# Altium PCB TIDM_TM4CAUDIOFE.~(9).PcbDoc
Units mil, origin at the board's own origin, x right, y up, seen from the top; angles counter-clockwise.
Board outline 2200 x 1200 mil, 4 copper layers (Component Side, Ground Plane, Power Plane, Solder Side), stack 33.234 mil thick; 32 components, 22 nets, 109 pads, 0 vias.
Unrouted connection lines stored in the file: 53.
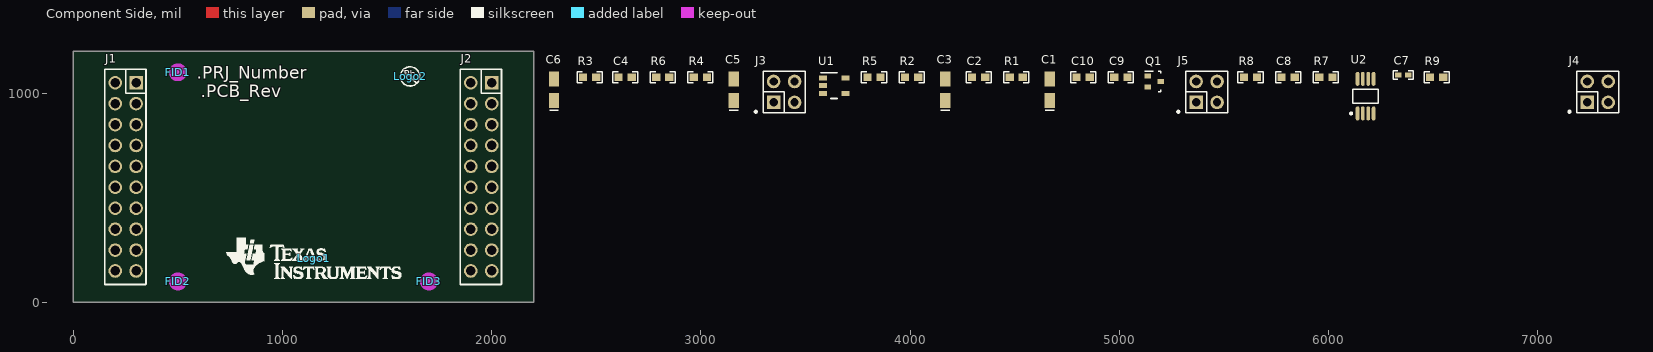
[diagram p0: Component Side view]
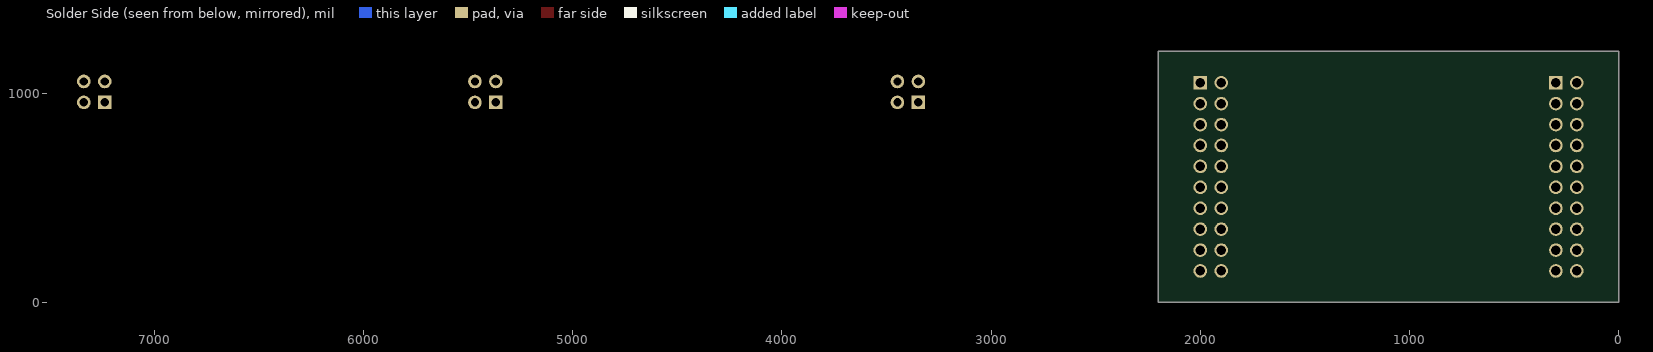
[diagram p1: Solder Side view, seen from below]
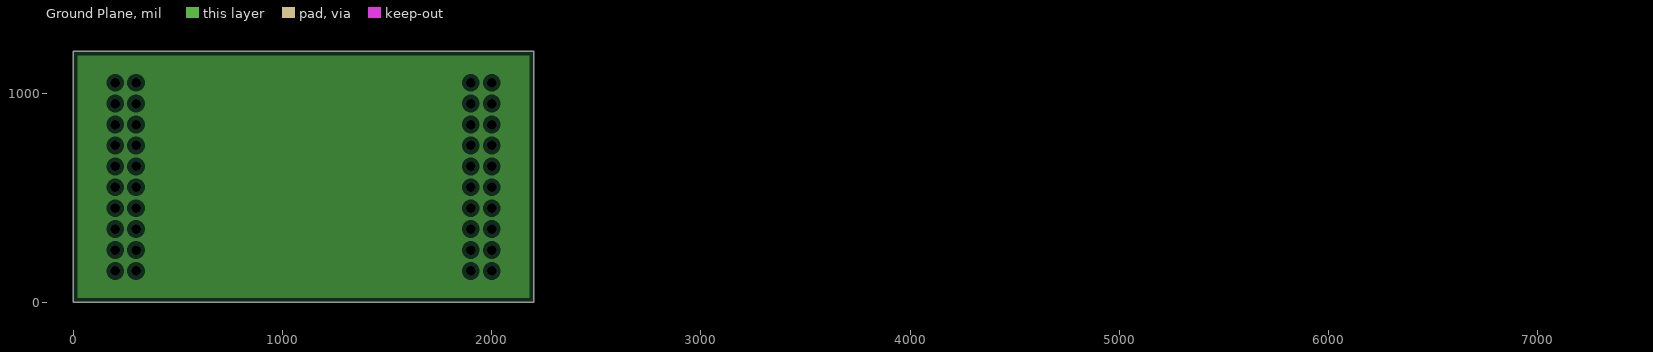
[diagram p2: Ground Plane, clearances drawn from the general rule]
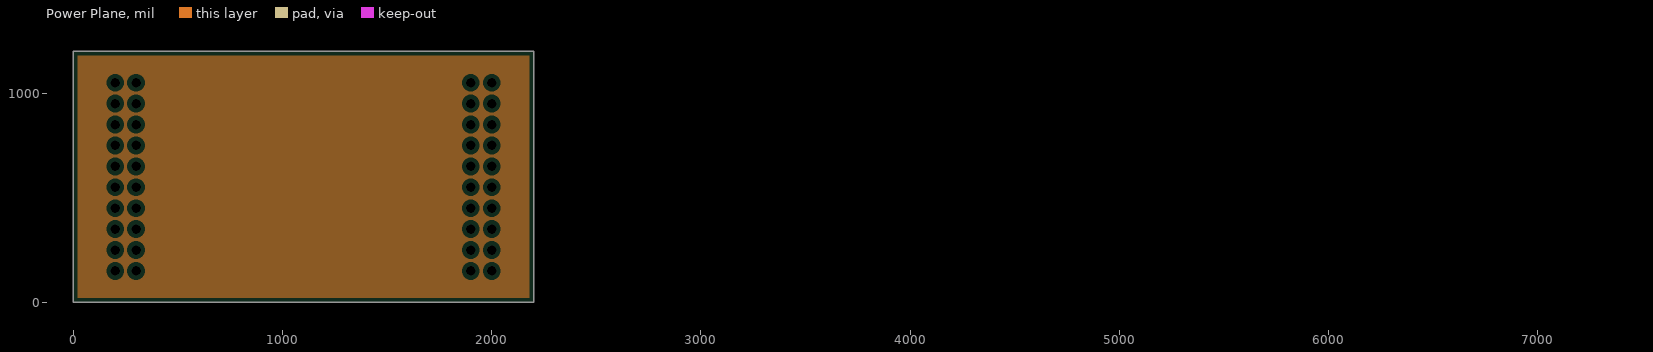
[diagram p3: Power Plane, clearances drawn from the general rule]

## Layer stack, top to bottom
Top Solder: solder mask 0.4, Solder Resist, Dk 3.5
Component Side: signal copper 1.4
Dielectric 1: core 12.6, FR-4, Dk 4.8
Ground Plane: plane copper 1.417
Dielectric 3: prepreg 5, Dk 4.2
Power Plane: plane copper 1.417
Dielectric 4: core 10, Dk 4.2
Solder Side: signal copper 1.4
Bottom Solder: solder mask 0.4, Solder Resist, Dk 3.5

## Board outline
0,0 0,1200 2200,1200 2200,0

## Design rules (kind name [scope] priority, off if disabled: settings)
AcuteAngle [All] p1: minimum=4.50000000000000E+0001 checktracksonly=FALSE
AssemblyTestPointUsage [All] p1: valid=2
Clearance Clearance_Keepouts [((IsTrack Or IsArc) And Not InPoly) And IsFree and IsKeepOut vs ((IsTrack Or IsArc) And Not InPoly) And IsFree and IsKeepOut] p1: gap=0
Clearance Clearance_BoardEdge_MountingHoles [OnCopper and InComponentClass('Mounting Holes') vs IsKeepOut] p2: gap=40
Clearance Clearance_BoardEdge_Poly [OnCopper and InPoly vs IsKeepOut] p3: gap=25
Clearance Clearance_BoardEdge [OnCopper and Not InComponentClass('Logo') and not InComponentClass('FiducialMark') and not InRegion(1000,500,4000,800) and Not IsKeepout vs IsKeepOut] p4: gap=75
Clearance Clearance_Poly [InPolygon] p5: gap=25
Clearance [All] p6: gap=7.87
ComponentClearance ComponentClearance_MountingHoles_FiducialMarks [InComponentClass('Mounting Holes') vs InComponentClass('FiducialMark')] p1: gap=50 collisioncheckmode=3 verticalgap=10 showdistances=FALSE
ComponentClearance ComponentClearance_Shunt [InComponentClass('Header') vs InComponentClass('Shunt')] p2: gap=0 collisioncheckmode=3 verticalgap=0 showdistances=FALSE
ComponentClearance ComponentClearance_Logo [InComponentClass('Logo')] p3: gap=50 collisioncheckmode=3 verticalgap=10 showdistances=FALSE
ComponentClearance ComponentClearance_ScrewToNut [(HasFootprint('NY PMS 440 0025 PH')) vs (HasFootprint('Keystone_1902C'))] p4: gap=5 collisioncheckmode=3 verticalgap=10 showdistances=FALSE
ComponentClearance ComponentClearance_MountingHoles [InComponentClass('Mounting Holes')] p5: gap=250 collisioncheckmode=3 verticalgap=100000 showdistances=FALSE
ComponentClearance ComponentClearance_SmallPassives [HasFootprint('0201*') or HasFootprint('0402*') or HasFootprint('0508') or HasFootprint('0603*') or HasFootprint('0612') or HasFootprint('0805*') or HasFootprint('0815*') or HasFootprint('0830*') or HasFootprint('1206*') or HasFootprint('1210*') or HasFootprint('1808*') or HasFootprint('1812*') or HasFootprint('1825*') or HasFootprint('2010*') or HasFootprint('2220*') or HasFootprint('2225*') or HasFootprint('2512*') or HasFootprint('2728*') or HasFootprint('3518*') vs HasFootprint('0201*') or HasFootprint('0402*') or HasFootprint('0508') or HasFootprint('0603*') or HasFootprint('0612') or HasFootprint('0805*') or HasFootprint('0815*') or HasFootprint('0830*') or HasFootprint('1206*') or HasFootprint('1210*') or HasFootprint('1808*') or HasFootprint('1812*') or HasFootprint('1825*') or HasFootprint('2010*') or HasFootprint('2220*') or HasFootprint('2225*') or HasFootprint('2512*') or HasFootprint('2728*') or HasFootprint('3518*')] p6: gap=20 collisioncheckmode=3 verticalgap=10 showdistances=FALSE
ComponentClearance ComponentClearance_THtoSMT [IsThruComponent vs IsSMTComponent] p7: gap=100 collisioncheckmode=3 verticalgap=30 showdistances=FALSE
ComponentClearance ComponentClearance_THtoTH [IsThruComponent vs IsThruComponent] p8: gap=118.11 collisioncheckmode=3 verticalgap=30 showdistances=FALSE
ComponentClearance [All] p9: gap=40 collisioncheckmode=3 verticalgap=10 showdistances=FALSE
DiffPairsRouting [All] p1: maxlimit=100 minlimit=10 mostfreqgap=10 toplayer_minwidth=15 toplayer_maxwidth=15 toplayer_prefwidth=15 bottomlayer_minwidth=15 bottomlayer_maxwidth=15 bottomlayer_prefwidth=15 maxuncoupledlength=1000
FabricationTestPointUsage TestPointUsage [All] p1: valid=2 allowmultiple=FALSE
FabricationTestpoint Testpoint [All] p1: side=3 testpointundercomponent=TRUE minsize=40 maxsize=100 preferedsize=60 minholesize=0 maxholesize=40 preferedholesize=32 testpointgrid=1 allowsidetop=TRUE allowsidebottom=TRUE usegrid=TRUE gridtolerance=0.01
FanoutControl Fanout_LCC [IsLCC] p1: bgadir=Out bgaviamode=Centered fanoutstyle=Auto fanoutdirection=Alternating viagrid=1 // Fanout_LCC (Default Rule)
FanoutControl Fanout_BGA [IsBGA] p2: bgadir=Out bgaviamode=Centered fanoutstyle=Auto fanoutdirection=Alternating viagrid=1 // Fanout_BGA (Default Rule)
FanoutControl Fanout_Default [All] p4: bgadir=Out bgaviamode=Centered fanoutstyle=Auto fanoutdirection=Alternating viagrid=1 // Fanout_Default (Default Rule)
FanoutControl Fanout_Small [(CompPinCount < 5)] p5: bgadir=Out bgaviamode=Centered fanoutstyle=Auto fanoutdirection=OutThenIn viagrid=1 // Fanout_Small (Default Rule)
HoleSize [All] p1: absolutevalues=TRUE maxlimit=251 minlimit=8 maxpercent=80.000 minpercent=20.000
MinimumAnnularRing MinimumAnnularRing_ThermalPadVias [IsVia and InAnyComponent] p1: minimumring=5.91
MinimumAnnularRing [All] p2: minimumring=9
MinimumSolderMaskSliver MinimumSolderMaskSliver_Logo [InComponentClass('Logo') vs InComponentClass('Logo')] p1: minsoldermaskwidth=0.7
MinimumSolderMaskSliver [All] p2: minsoldermaskwidth=3.94
PlaneClearance [All] p1: clearance=20
PlaneConnect [All] p1: planeconnectstyle=Relief reliefexpansion=10 reliefentries=4 reliefconductorwidth=10 reliefairgap=10
PolygonConnect [All] p1: connectstyle=Relief reliefconductorwidth=10 reliefentries=4 polygonreliefangle="90 Angle" airgapwidth=10
RoutingVias ThermalPadVias [IsVia and InAnyComponent] p1: holewidth=7.87 width=19.68 viastyle="Through Hole" minholewidth=7.87 minwidth=19.68 maxholewidth=12.99 maxwidth=23.62
RoutingVias [All] p2: holewidth=16 width=34 viastyle="Through Hole" minholewidth=7.87 minwidth=26 maxholewidth=40 maxwidth=65
SilkToBoardRegionClearance [Not ((IsComment or IsDesignator) And (Hide <> 'False')) and not InRegion(1000,500,4000,800)] p1:
SilkToSilkClearance SilkToSilkClearance_Pb-FreeLogo [(HasFootprint('Pb-Free_Overlay_Medium') OR HasFootprint('Pb-Free_Overlay_Small')) vs (HasFootprint('Pb-Free_Overlay_Medium') OR HasFootprint('Pb-Free_Overlay_Small'))] p1: silktosilkclearance=0
SilkToSilkClearance [All] p2: silktosilkclearance=4
SilkToSolderMaskClearance SilkToComonentPadClearance [IsPad and InAnycomponent] p1: minsilkscreentomaskgap=5 clearancetoexposedcopper=TRUE
SilkToSolderMaskClearance "Silk to Solder Mask Opening" [All] p2: minsilkscreentomaskgap=4 clearancetoexposedcopper=FALSE
SolderMaskExpansion [All] p1: expansion=1.97
UnpouredPolygon [All] p1: allowunpoured=FALSE
Width [All] p1: maxlimit=100 minlimit=6 preferedwidth=10 checkconnectedcopper=TRUE
13 further rules are at their usual default settings.

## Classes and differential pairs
component class Header: J3 J4 J5
component class Logo: Logo1
component class FiducialMark: FID1 FID2 FID3

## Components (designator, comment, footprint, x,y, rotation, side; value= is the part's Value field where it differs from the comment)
C1 "TPSA225K010R1800" 3216-18 4668,1016 r90 top
C2 "GRM1885C1H160JA01D" 0603 4328,1076 r0 top
C3 "TPSA225K010R1800" 3216-18 4168,1016 r90 top
C4 "0603YC104JAT2A" 0603 2638,1076 r0 top
C5 "TPSA225K010R1800" 3216-18 3158,1016 r90 top
C6 "TPSA225K010R1800" 3216-18 2298,1016 r90 top
C7 "GRM1555C1H751JA01D" 0402 6358,1086 r0 top
C8 "GRM188R71C473KA01D" 0603 5808,1076 r0 top
C9 "GRM188R71A474KA61D" 0603 5008,1076 r0 top
C10 "GRM188R71E105KA12D" 0603 4828,1076 r0 top
FID1 "Fiducial" Fiducial10-20 500,1100 r0 top
FID2 "Fiducial" Fiducial10-20 500,100 r0 top
FID3 "Fiducial" Fiducial10-20 1700,100 r0 top
J1 "SSW-110-23-F-D" CONN_SSW-110-23-F-D 250,600 r90 top
J2 "SSW-110-23-F-D" CONN_SSW-110-23-F-D 1950,600 r90 top
J3 "TSW-102-07-G-D" TSW-102-07-G-D 3398,1006 r0 top
J4 "TSW-102-07-G-D" TSW-102-07-G-D 7288,1006 r0 top
J5 "TSW-102-07-G-D" TSW-102-07-G-D 5418,1006 r0 top
Logo1 "Texas Instruments" TI_Stacked_Overlay_Small 1150,210 r0 top
Logo2 "Pb-Free Symbol" Pb-Free_Overlay_Small 1610,1080 r0 top
Q1 "DTC114EUAT106" SOT-323 5168,1056 r0 top
R1 "RC0603FR-073K6L" 0603 4508,1076 r0 top
R2 "RC0603FR-0775KL" 0603 4008,1076 r0 top
R3 "RC0603FR-07100KL" 0603 2468,1076 r0 top
R4 "RC0603FR-0749R9L" 0603 2998,1076 r0 top
R5 "RC0603FR-07100KL" 0603 3828,1076 r0 top
R6 "RC0603FR-07100KL" 0603 2818,1076 r0 top
R7 "RC0603FR-0710KL" 0603 5988,1076 r0 top
R8 "RC0603FR-0720KL" 0603 5628,1076 r0 top
R9 "RC0603FR-0720KL" 0603 6518,1076 r0 top
U1 "OPA322AIDBVR" DBV0005A_N 3638,1036 r0 top
U2 "LM4819MM" MUA08A_N 6178,986 r90 top

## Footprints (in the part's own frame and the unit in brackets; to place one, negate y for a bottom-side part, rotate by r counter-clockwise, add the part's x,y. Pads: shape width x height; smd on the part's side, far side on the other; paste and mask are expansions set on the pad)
0402 [mm] "0402 from SM-752 data"
  rect 0.8x0.6 smd: 1(-0.6,0) 2(0.6,0)
  silkscreen extent -1.22,-0.52 1.22,0.52, body extent -0.55,-0.3 0.55,0.3, height 0.6
0603 [mm] "0603 from SM-752 data"
  rect 1x0.95 smd: 1(-0.8,0) 2(0.8,0)
  silkscreen extent -1.52,-0.69 1.52,0.69, body extent -0.87,-0.47 0.87,0.47, height 1
3216-18 [mm] "Medium density IPC, based on Kemet T495 dimensions"
  rect 1.8x1.25 smd: 1(-1.3,0) 2(1.3,0)
  silkscreen extent -2.49,-0.54 -2.49,0.54, body extent -1.7,-0.9 1.7,0.9, height 1.8
CONN_SSW-110-23-F-D [mm] "SAMTEC"
  rect 1.65x1.65 hole 1.15: 1(11.43,-1.27)
  round 1.65 hole 1.15: 2(11.43,1.27) 3(8.89,-1.27) 4(8.89,1.27) 5(6.35,-1.27) 6(6.35,1.27) 7(3.81,-1.27) 8(3.81,1.27) 9(1.27,-1.27) 10(1.27,1.27) 11(-1.27,-1.27) 12(-1.27,1.27) 13(-3.81,-1.27) 14(-3.81,1.27) 15(-6.35,-1.27) 16(-6.35,1.27) 17(-8.89,-1.27) 18(-8.89,1.27) 19(-11.43,-1.27) 20(-11.43,1.27)
  silkscreen extent -13.08,-2.46 13.08,2.54, body extent -13,-2.51 13,2.54, height 8.59
DBV0005A_N [mm] "SOT23, 5-Leads, Body 2.9x1.6mm, Pitch 0.95mm, Lead Span 2.8mm, IPC Medium Density"
  rrect17% 1x0.6 smd: 1(-1.375,0.95) 2(-1.375,0) 3(-1.375,-0.95) 4(1.375,-0.95) 5(1.375,0.95)
  silkscreen extent -1.63,-1.55 0.38,1.55, body extent -1.42,-1.46 1.42,1.46, height 1.09
Fiducial10-20 [mm]
  round 1 smd mask+0.5: 1(0,0)
  Component Side keep-out circle w1.178: c0,0 r0.5
MUA08A_N [mm] "TSOP, 8-Leads, Body 3x3mm, Pitch 0.65mm, IPC Medium Density"
  oval 1.7x0.45 smd: 1(-2.1,0.975) 2(-2.1,0.325) 3(-2.1,-0.325) 4(-2.1,-0.975) 5(2.1,-0.975) 6(2.1,-0.325) 7(2.1,0.325) 8(2.1,0.975)
  silkscreen extent -2.22,-1.55 0.85,1.87, body extent -1.6,-1.6 1.6,1.6, height 1.09
Pb-Free_Overlay_Small [mil]
  silkscreen extent -46,-46 46,46
SOT-323 [mm] "Zetex recommended land pattern.  March 2007"
  rect 0.8x0.6 smd: 1(-0.8,0.65) 2(-0.8,-0.65) 3(0.8,0)
  silkscreen extent -1.14,-1.22 0.77,1.22, body extent -1.13,-1.13 1.12,1.12, height 1.13
TI_Stacked_Overlay_Small [mil]
  silkscreen extent -418,-98 418,98
TSW-102-07-G-D [mm] "Samtec 100mil, 2x2, 230 mil above insulator"
  rect 1.65x1.65 hole 1.016 mask+0: 1(-1.27,-1.27)
  round 1.65 hole 1.016 mask+0: 2(-1.27,1.27) 3(1.27,-1.27) 4(1.27,1.27)
  silkscreen extent -3.56,-2.54 2.54,2.54, body extent -2.54,-2.54 2.54,2.54, height 8.38

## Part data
C1 C3 C5 C6: "CAP, TA, 2.2 µF, 10 V, +/- 10%, 1.8 ohm, SMD"
C2: "CAP, CERM, 16 pF, 50 V, +/- 5%, C0G/NP0, 0603"
C4: "CAP, CERM, 0.1 µF, 16 V, +/- 5%, X7R, 0603"
C7: "CAP, CERM, 750 pF, 50 V, +/- 5%, C0G/NP0, 0402"
C8: "CAP, CERM, 0.047 µF, 16 V, +/- 10%, X7R, 0603"
C9: "CAP, CERM, 0.47 µF, 10 V, +/- 10%, X7R, 0603"
C10: "CAP, CERM, 1 µF, 25 V, +/- 10%, X7R, 0603"
FID1 FID2 FID3: "Fiducial mark.  There is nothing to buy or mount."
J1 J2: "Connector, Receptacle, 100mil, 10x2, Gold plated, TH"
J3 J4 J5: "Header, 100mil, 2x2, Gold, TH"
Logo1: library part TI_Logo, "Texas Instrument Corporate Signature"
Logo2: library part Pb-Free
Q1: library part "DTC114EUAT106, Rohm", "Transistor, NPN, 50 V, 0.05 A, SOT-323"
R1: "RES, 3.60 k, 1%, 0.1 W, 0603"
R2: "RES, 75.0 k, 1%, 0.1 W, 0603"
R3 R5 R6: "RES, 100 k, 1%, 0.1 W, 0603"
R4: "RES, 49.9, 1%, 0.1 W, 0603"
R7: "RES, 10.0 k, 1%, 0.1 W, 0603"
R8 R9: "RES, 20.0 k, 1%, 0.1 W, 0603"
U1: "20 MHz, Low Noise, RRIO, CMOS Operational Amplifier with Shutdown, 1.8 to 5.5 V, -40 to 125 degC, 5-pin SOT23 (DBV0005A), Green (RoHS & no Sb/Br)"
U2: "350mW Audio Power Amplifier with Shutdown Mode, 8-pin Mini SOIC"

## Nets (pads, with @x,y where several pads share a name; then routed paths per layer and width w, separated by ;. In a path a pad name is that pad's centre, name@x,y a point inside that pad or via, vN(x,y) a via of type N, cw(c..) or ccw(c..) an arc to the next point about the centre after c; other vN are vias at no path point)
GND: C1.2 C4.2 C6.2 C9.2 C10.2 J1.3 J2.1 Q1.2 R3.1 R6.1 U1.2 U2.7
MICOUT0: J1.4 J3.2
MICOUT1: J1.12 J3.4
MICOUT_S: C5.2 J3.1 J3.3 R6.2
NetC2_1: C2.1 R2.2 R4.1 U1.1
NetC2_2: C2.2 C3.1 R2.1 U1.4
NetC3_2: C3.2 R1.1
NetC5_1: C5.1 R4.2
NetC6_1: C6.1 R3.2 R5.1 U1.3
NetC7_1: C7.1 R9.2 U2.5
NetC7_2: C7.2 R8.2 R9.1 U2.4
NetC8_1: C8.1 R8.1
NetC9_1: C9.1 U2.2 U2.3
NetQ1_3: Q1.3 R7.1 U2.1
SPKEN0: J2.17 J5.2
SPKEN1: J2.19 J5.4
SPKEN_S: J5.1 J5.3 Q1.1
SPKOUT0: J2.3 J4.2
SPKOUT1: J2.11 J4.4
SPKOUT_S: C8.2 J4.1 J4.3
VCC_3P3: C1.1 C4.1 J1.2 R1.2 R5.2 U1.5
VCC_5P0: C10.1 J1.1 R7.2 U2.6
pads on no net: FID1.1 FID2.1 FID3.1 J1.5 J1.6 J1.7 J1.8 J1.9 J1.10 J1.11 J1.13 J1.14 J1.15 J1.16 J1.17 J1.18 J1.19 J1.20 J2.2 J2.4 J2.5 J2.6 J2.7 J2.8 J2.9 J2.10 J2.12 J2.13 J2.14 J2.15 J2.16 J2.18 J2.20 U2.8

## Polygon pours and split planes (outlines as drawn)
no net on Ground Plane (split plane): 2179.9,20.1 20.1,20.1 20.1,1179.9 2179.9,1179.9
no net on Power Plane (split plane): 2179.9,20.1 20.1,20.1 20.1,1179.9 2179.9,1179.9

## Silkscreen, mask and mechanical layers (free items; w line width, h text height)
Top Overlay:
  text ".PRJ_Number" at 590,1070 h60
  text ".PCB_Rev" at 610,980 h60
Mechanical 1:
  the board outline again, w10
Mechanical 2:
  rectangle: 0,-275 125,-150
  rectangle: 125,-400 500,-275
  lines w7: 0,-275 1000,-275 ; 125,-400 125,-150 ; 250,-400 250,-150 ; 500,-400 500,-150 ; 750,-400 750,-150 ; 0,-400 1000,-400 1000,-150 0,-150 0,-400
  text ".Layer_Name" at 577,-858.49 h60
Mechanical 3:
  text ".Layer_Name" at 577,-858.49 h60
Mechanical 4:
  text ".Layer_Name" at 577,-858.49 h60
Mechanical 5:
  lines w10: -292,-930.17 6308,-930.17 ; -292,-726.83 6310,-726.83 ; -292,-523.5 -292,-1133.5 3713,-1133.5 6310,-1133.5 6310,-523.5 -291.5,-523.5 -291.5,-1133.5 1284,-1133.5 ; 2173,-1133.5 2173,-523.5 ; 3440,-726.83 3440,-523.5 ; 4280,-726.83 4280,-523.5 ; 4902,-1140 4902,-937.17
  text "COMPONENTS MARKED 'DNP' SHOULD NOT BE POPULATED." at 1153.5,-318.5 h60
  text "ASSEMBLY VARIANT:" at 1153,-434 h60
  text ".VariantName" at 2189,-434 h60
  text "PCB VIEWED FROM TOP SIDE" at -228.5,-655.67 h60
  text "BOARD #:" at 2248,-655.67 h60
  text ".PRJ_Number" at 2793.5,-655.67 h60
  text "REV:" at 3638,-655.67 h60
  text ".PCB_Rev" at 3929.5,-655.67 h60
  text "SVN REV:" at 4476,-655.67 h60
  text ".VersionControl_RevNumber" at 4982,-655.67 h60
  text "TID #:" at 2248,-859 h60
  text ".TID" at 2793.5,-859 h60
  text "PLOT NAME =" at -228.5,-1064.34 h60
  text ".plot_File_Name" at 577,-1064.34 h60
  text "GENERATED    :" at 2250,-1064.34 h60
  text ".Print_Date" at 3119.5,-1064.34 h60
  text ".Print_Time" at 3848.5,-1064.34 h60
  text "TEXAS INSTRUMENTS" at 5113,-1064.34 h60
Mechanical 6:
  lines w10: -292.5,-727.33 6309.5,-727.33 ; -290.5,-930.67 6309.5,-930.67 ; 1115.5,-1140.5 1115.5,-937.67 ; 1737.5,-727.33 1737.5,-524 ; 2577.5,-727.33 2577.5,-524 ; 3844.5,-1134 3844.5,-524 ; 4733.5,-1134 6309,-1134 6309,-524 -292.5,-524 -292.5,-1134 2304.5,-1134 6309.5,-1134 6309.5,-524
  text "COMPONENTS MARKED 'DNP' SHOULD NOT BE POPULATED." at 6102,-318 h60
  text ".VariantName" at 5058,-434 h60
  text "ASSEMBLY VARIANT:" at 6097,-434 h60
  text ".VersionControl_RevNumber" at 1035.5,-656.17 h60
  text "SVN REV:" at 1541.5,-656.17 h60
  text ".PCB_Rev" at 2088,-656.17 h60
  text "REV:" at 2379.5,-656.17 h60
  text ".PRJ_Number" at 3224,-656.17 h60
  text "BOARD #:" at 3769.5,-656.17 h60
  text "PCB VIEWED FROM BOTTOM SIDE" at 6246,-656.17 h60
  text ".TID" at 3224,-859.5 h60
  text "TID #:" at 3769.5,-859.5 h60
  text "TEXAS INSTRUMENTS" at 904.5,-1064.84 h60
  text ".Print_Time" at 2169,-1064.84 h60
  text ".Print_Date" at 2898,-1064.84 h60
  text "GENERATED    :" at 3767.5,-1064.84 h60
  text ".plot_File_Name" at 5440.5,-1064.84 h60
  text "PLOT NAME =" at 6246,-1064.84 h60
Mechanical 9:
  drawing of 57 lines, arcs and shapes, not listed
  text "1" at 739.84,8036.5 h70
  text "2" at 3235.5,8036.5 h70
  text "3" at 5724.84,8036.5 h70
  text "4" at 8231.51,8036.5 h70
  text "5" at 10730.5,8036.5 h70
  text "6" at 13235.5,8036.5 h70
  text "A" at -416.5,6893.5 h70
  text "A" at 14383.5,6893.5 h70
  text "B" at -416.5,4513.5 h70
  text "B" at 14383.5,4513.5 h70
  text "C" at -416.5,2138.5 h70
  text "C" at 14383.5,2138.5 h70
  text "PROJECT TITLE:" at 11343.5,277.5 h45
  text ".PRJ_Title" at 11393.5,144.17 h70
  text "DESIGNED FOR:" at 11343.5,-23.5 h45
  text ".PRJ_Customer" at 11393.5,-163.5 h70
  text "D" at -416.5,-231.5 h70
  text "D" at 14383.5,-231.5 h70
  text "FILE NAME:" at 11343.5,-323.5 h45
  text ".PCB_File_Name_No_Path" at 11393.5,-443.5 h70
  text "Texas Instruments (TI) and/or its licensors do not warrant the accuracy or completeness of this specification" at 6374,-605.34 h45
  text "ENGINEER:" at 11343.5,-613.5 h45
  text "LAYOUT BY:" at 12848.5,-613.5 h45
  text "or any information contained therein. TI and/or its licensors do not warrant that this design will meet" at 6329.01,-718 h45
  text ".PRJ_Engineer" at 11393.5,-768.49 h70
  text ".PCB_Layout" at 12899,-768.49 h70
  text "the specifications, will be suitable for your application or fit for any particular purpose, or will operate in" at 6329.01,-830.67 h45
  text ".Layer_Name" at 577,-858.49 h60
  text "ALTIUM DESIGNER VERSION:" at 12848.5,-923.5 h45
  text "an implementation. TI and/or its licensors do not warrant that the design is production worthy. You should" at 6329.01,-943.33 h45
  text "completely validate and test your design implementation to confirm the system functionality for your application." at 6374,-1056 h45
  text ".print_Scale" at 11393.5,-1056.83 h70
  text ".Application_BuildNumber" at 12899,-1056.83 h70
  text "1" at 739.84,-1263.5 h70
  text "2" at 3235.5,-1263.5 h70
  text "3" at 5724.84,-1263.5 h70
  text "4" at 8231.51,-1263.5 h70
  text "5" at 10730.5,-1263.5 h70
  text "6" at 13235.5,-1263.5 h70
Mechanical 10:
  drawing of 173 lines, arcs and shapes, not listed
  text "DESIGN INFORMATION" at 12377.02,6201 h60
  text "MIN. TRACK WIDTH:" at 11732.46,6021 h60
  text "8" at 12828.7,6021 h60
  text "MIL" at 12983.46,6021 h60
  text "MIN. CLEARANCE:" at 11732.46,5889 h60
  text "0.2" at 12768.7,5889 h60
  text "mm" at 12983.46,5889 h60
  text "MIN. VIA PAD SIZE:" at 11732.46,5757 h60
  text "24" at 12798.71,5757 h60
  text "MIL" at 12983.46,5757 h60
  text "0.05mm (2MIL)" at 12427.46,5615.29 h60
  text "MINIMUM ANNULAR RING" at 11403.23,5611 h60
  text "EXTERNAL" at 13135.46,5611 h60
  text "PER" at 11603.23,5493 h60
  text "IPC-D-275 CLASS 2 LEVEL C" at 11823.23,5493 h60
  text "MIL, HOLES" at 13311.46,5380.71 h60
  text "+/-" at 12919,5380 h60
  text "+/-" at 13773,5380 h60
  text "REGISTRATION TOLERANCES:" at 11403.23,5375 h60
  text "METAL" at 12603,5375 h60
  text "5" at 13179.2,5375 h60
  text "3" at 14012.2,5375 h60
  text "MIL" at 14128.46,5375 h60
  text "+/-" at 13773,5262 h60
  text "HOLE SIZE TOLERANCE (UNLESS OTHERWISE SPECIFIED):" at 11403.23,5257 h60
  text "3" at 14012.2,5257 h60
  text "MIL" at 14128.46,5257 h60
  text "MATERIAL:" at 11328.46,5047.54 h60
  text "FR-4 High Tg" at 12314.9,4907.21 h60
  text "FR-408" at 11749.46,4898.64 h60
  text "OTHER" at 13237.46,4898.64 h60
  text "X" at 12160,4895 h60
  text "62 MIL (1.6mm) +/-10%" at 12069.56,4735.92 h60
  text "THICKNESS:" at 11403.23,4731.64 h60
  text "X" at 11941.4,4731.64 h60
  text "OTHER" at 13354.46,4731.64 h60
  text "TOLERANCE:" at 11403.23,4573.64 h60
  text "X" at 12242.53,4573.64 h60
  text "ANSI IPC-6012 TYPE 3 CLASS 2" at 12429.48,4573.64 h60
  text "OTHER +/-" at 12429.46,4417.64 h60
  text "BOW & TWIST:" at 11403.23,4260.64 h60
  text "X" at 12242.53,4260.64 h60
  text "ANSI IPC-6012 TYPE 3 CLASS 2" at 12429.48,4260.64 h60
  text "OTHER +/-" at 12429.46,4102.13 h60
  text "DRILLING:" at 11328.46,3963.64 h60
  text "REFERENCE:" at 11403.23,3846.64 h60
  text "X" at 12051.46,3846.64 h60
  text "AS SHOWN" at 12238.46,3846.64 h60
  text "X" at 12952.46,3846.64 h60
  text "NC_DRILL FILES" at 13089.46,3846.64 h60
  text "PTH MIN COPPER THICKNESS:" at 11403.23,3688.64 h60
  text "X" at 12753.46,3688.64 h60
  text "1MIL" at 12890.46,3688.64 h60
  text "OTHER" at 13387.46,3688.64 h60
  text "BOARD FINISH:" at 11328.46,3529.64 h60
  text "SILKSCREEN:" at 11483.68,3411.64 h60
  text "X" at 12432.46,3411.64 h60
  text "TOP" at 12558.46,3411.64 h60
  text "X" at 12942.46,3411.64 h60
  text "BOTTOM" at 13069.46,3411.64 h60
  text "SILKSCREEN COLOR:" at 11483.68,3244.64 h60
  text "X" at 12431.42,3244.64 h60
  text "WHITE" at 12558.46,3244.64 h60
  text "OTHER" at 13069.46,3244.64 h60
  text "X" at 12562.42,3085.44 h60
  text "GREEN" at 12689.46,3085.44 h60
  text "OTHER" at 13307.46,3085.44 h60
  text "SOLDER RESIST COLOR:" at 11483.68,3074.64 h60
  text "X" at 12562.42,2915.44 h60
  text "MATTE" at 12689.46,2915.44 h60
  text "SEMI-GLOSS" at 13307,2914.8 h60
  text "IMMERSION GOLD (ENIG)" at 12389.46,2726.92 h60
  text "ENEPIG" at 13727,2723.64 h60
  text "SURFACE FINISH:" at 11328.46,2722.64 h60
  text "X" at 12202.51,2722.64 h60
  text "IMM. TIN/SILVER OR EQUIV" at 11658,2565.64 h60
  text "OTHER" at 13089.46,2565.64 h60
  text "ARRAY/PANEL:" at 11328.46,2386.64 h60
  text "CUT AND TRIM PER M1 BOARD OUTLINE" at 12389.46,2382.35 h60
  text "N.C. ROUTE" at 12389.46,2230.64 h60
  text "X" at 13068.46,2230.64 h60
  text "V. SCORE" at 13255.46,2230.64 h60
  text "CERTIFICATION:" at 11328.46,2093.64 h60
  text "MATERIALS AND WORKMANSHIP FOR ALL PCBS" at 12053.46,2093.64 h60
  text "TO MEET OR EXCEED THE REQUIREMENTS OF:" at 12053.46,1995.64 h60
  text "X" at 11679.96,1859.13 h60
  text "ANSI IPC-A-600F CLASS ->" at 11818.96,1859.13 h60
  text "X" at 13458.02,1859.13 h60
  text "2" at 13576.96,1859.14 h60
  text "1" at 13261.96,1857.64 h60
  text "3" at 13930.96,1857.64 h60
  text "X" at 12494.02,1699.64 h60
  text "RoHS" at 12630.96,1699.64 h60
  text "OTHER" at 13275.36,1699.64 h60
  text "PER ORDER" at 13672.42,1699.64 h60
  text "ALL BOARDS MUST MEET OR EXCEED UL94-V0 REQUIREMENTS." at 11356,1534 h60
  text "PCB MUST BEAR THE UL94V-0 UL REGISTERED MATERIAL ID NUMBER" at 11356,1414 h60
  text "ADDITIONAL REQUIREMENTS:" at 11328.46,1240.64 h60
  text "MICROSECTION:" at 11403.23,1125.64 h60
  text "YES" at 12308.96,1125.64 h60
  text "REQUIRED" at 13170.46,969.49 h60
  text "BARE BOARD ELEC. TEST:" at 11403.23,966.64 h60
  text "NONE" at 12708.96,966.64 h60
  text "X" at 13043.46,966.64 h60
  text "PER ORDER" at 13762.46,966.64 h60
  text ".Layer_Name" at 577,-858.49 h60
Mechanical 11:
  lines w10: -292,-930.17 6308,-930.17 ; -292,-726.83 6310,-726.83 ; -292,-523.5 -292,-1133.5 3713,-1133.5 6310,-1133.5 6310,-523.5 -291.5,-523.5 -291.5,-1133.5 1284,-1133.5 ; 2173,-1133.5 2173,-523.5 ; 3440,-726.83 3440,-523.5 ; 4280,-726.83 4280,-523.5 ; 4902,-1140 4902,-937.17
  text "ALL ARTWORK VIEWED FROM TOP SIDE" at -228.5,-655.67 h60
  text "BOARD #:" at 2248,-655.67 h60
  text ".PRJ_Number" at 2793.5,-655.67 h60
  text "REV:" at 3638,-655.67 h60
  text ".PCB_Rev" at 3929.5,-655.67 h60
  text "SVN REV:" at 4476,-655.67 h60
  text ".VersionControl_RevNumber" at 4982,-655.67 h60
  text "LAYER NAME =" at -228.5,-858.49 h60
  text "TID #:" at 2248,-859 h60
  text ".TID" at 2793.5,-859 h60
  text "PLOT NAME =" at -228.5,-1064.34 h60
  text ".plot_File_Name" at 577,-1064.34 h60
  text "GENERATED    :" at 2250,-1064.34 h60
  text ".Print_Date" at 3119.5,-1064.34 h60
  text ".Print_Time" at 3848.5,-1064.34 h60
  text "TEXAS INSTRUMENTS" at 5113,-1064.34 h60
Mechanical 12:
  drawing of 191 lines, arcs and shapes, not listed
  text "Layer" at 9790.58,7830 h60
  text "Name" at 10200.49,7830 h60
  text "Material" at 11130.23,7830 h60
  text "Thickness" at 11990,7830 h60
  text "Constant" at 12639.84,7830 h60
  text "Board Layer Stack" at 13209.7,7830 h60
  text "1" at 9790.58,7710 h60
  text "Top Overlay" at 10200.49,7710 h60
  text "2" at 9790.58,7590 h60
  text "Top Solder" at 10200.49,7590 h60
  text "Solder Resist" at 11130.23,7590 h60
  text "0.40mil" at 11990,7590 h60
  text "3.5" at 12639.84,7590 h60
  text "3" at 9790.58,7470 h60
  text "Top Layer" at 10200.49,7470 h60
  text "Copper" at 11130.23,7470 h60
  text "1.40mil" at 11990,7470 h60
  text "4" at 9790.58,7350 h60
  text "Dielectric1" at 10200.49,7350 h60
  text "FR-4" at 11130.23,7350 h60
  text "59.20mil" at 11990,7350 h60
  text "4.8" at 12639.84,7350 h60
  text "5" at 9790.58,7230 h60
  text "Bottom Layer" at 10200.49,7230 h60
  text "Copper" at 11130.23,7230 h60
  text "1.40mil" at 11990,7230 h60
  text "6" at 9790.58,7110 h60
  text "Bottom Solder" at 10200.49,7110 h60
  text "Solder Resist" at 11130.23,7110 h60
  text "0.40mil" at 11990,7110 h60
  text "3.5" at 12639.84,7110 h60
  text "7" at 9790.58,6990 h60
  text "Bottom Overlay" at 10200.49,6990 h60
  text ".Layer_Name" at 577,-858.49 h60
Mechanical 13:
  text ".Layer_Name" at 577,-858.49 h60
Mechanical 14:
  text ".Layer_Name" at 577,-858.49 h60
Mechanical 15:
  text ".Layer_Name" at 577,-858.49 h60
Mechanical 16:
  text ".Layer_Name" at 577,-858.49 h60

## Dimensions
0,-400 to 1000,-400 on Mechanical 2
0,0 to 2200,0 on Mechanical 2
0,0 to 0,1200 on Mechanical 2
